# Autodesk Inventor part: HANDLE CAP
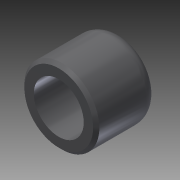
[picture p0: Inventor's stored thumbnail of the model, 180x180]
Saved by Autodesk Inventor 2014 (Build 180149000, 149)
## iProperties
Shininess: 64.0
Length Units: 11272
Angle Units: 11279
Time Units: 11290
Mass Units: 11286
Length Display Precision: 3
Angle Display Precision: 2
Compacted: True
Part Number: HANDLE CAP
Document SubType Name: Modeling
Created: 2003-11
Designer: Autodesk, Inc.
Manufacturer: Standard
Standards Organization: Custom
Mass: 2.20956 g
Surface Area: 17.857 cm^2
Volume: 2.37587 cm^3
Density: 0.93 g/cm^3
Material: Rubber
Appearance: Smooth - Medium Gray
Density: 0.0
Volumn: 0.0
Area: 0.0
PropertySet Name: Model Information
Control State: 0
Master: False
Checked Out: False
Author: Autodesk, Inc.
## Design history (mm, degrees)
sketch "Sketch1"
  geometry: C1 r 9.525 at (0, 0); C2 r 6.35 at (0, 0); 1 further point
  constraints: 2 centre point, 2 coincident
  dimensions: "d0" = 19.05 diameter of C1; "d1" = 12.7 diameter of C2
extrude "Extrusion1" new body sketch "Sketch1" distance "d2" = 15.875; taper "d3" = 0 deg
chamfer "Chamfer1" distance "d5" = 0.7874; stored, may be unused: second distance "d6" = 3.175, angle "d7" = 45 deg
fillet "Fillet2" dims "d8" = 3.175
body "Solid1"
